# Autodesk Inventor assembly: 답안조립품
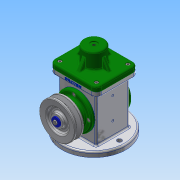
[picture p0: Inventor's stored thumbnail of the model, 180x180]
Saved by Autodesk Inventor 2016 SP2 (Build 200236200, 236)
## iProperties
Created: 2018-10
Part Number: 답안조립품
Document SubType Name: Assembly
Designer: Administrator
Author: Administrator
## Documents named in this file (18)
- Y:\481007V1005 이주헌\답안조립품.iam
- Y:\481007V1005 이주헌\본체.ipt
- Y:\481007V1005 이주헌\E-링.ipt
- Y:\481007V1005 이주헌\V-벨트풀리.ipt
- Y:\481007V1005 이주헌\덮개.ipt
- Y:\481007V1005 이주헌\뒤커버.ipt
- Y:\481007V1005 이주헌\링크.ipt
- Y:\481007V1005 이주헌\베어링 17 x 40 x 12.ipt
- Y:\481007V1005 이주헌\볼트 M4 x 8.ipt
- Y:\481007V1005 이주헌\볼트 M4 x 10.ipt
- Y:\481007V1005 이주헌\슬라이더.ipt
- Y:\481007V1005 이주헌\앞커버.ipt
- Y:\481007V1005 이주헌\오일 실 17 30 8.ipt
- Y:\481007V1005 이주헌\와셔 4x16.ipt
- Y:\481007V1005 이주헌\클레비스 핀 6 x 22.ipt
- 클레비스 핀 6 x 22.ipt
- Y:\481007V1005 이주헌\키 4 x 4 x 12.ipt
- Y:\481007V1005 이주헌\편심축.ipt
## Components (2 placed, 2 different names)
1. E-링:1
2. V-벨트풀리:1 — 각도:2
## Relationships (1: Angle 1)
- 각도:2 [Angle]: V-벨트풀리:1
